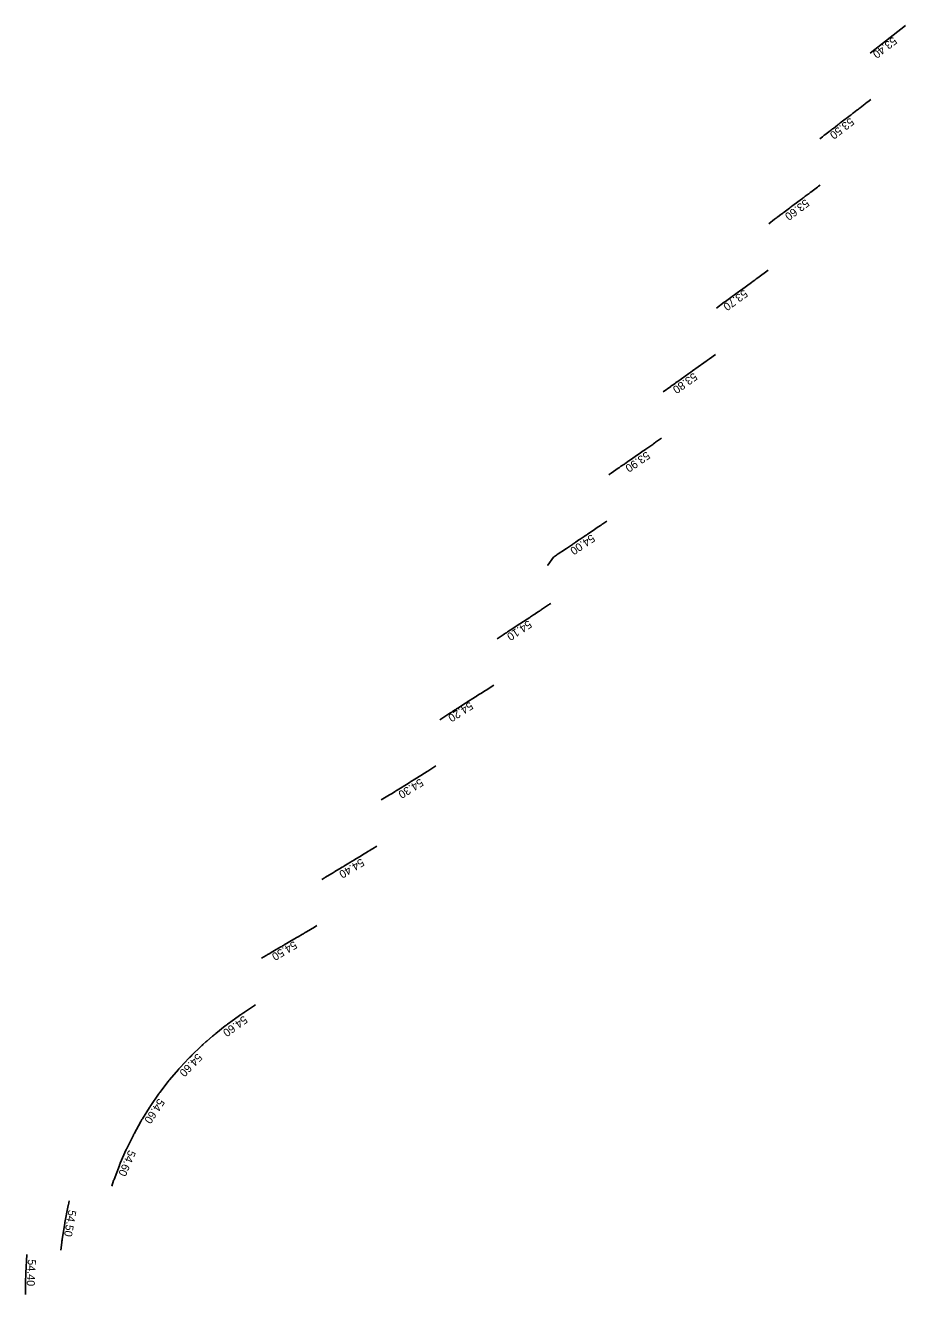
# Model space of a CAD drawing. Extents: x 655100 to 703495, y 6445581 to 6476602.
# Drawn here: x 668502.6 to 668612.5, y 6466301.5 to 6466460 of the extents above; entities that cross this region are included whole.
import ezdxf

# ---------------------------------------------------------------- set-up
doc = ezdxf.new("R2010")
doc.units = 0
for name, color, linetype in [('horis_01', 7, 'Continuous'), ('horis_1', 7, 'Continuous'), ('horis_korgusarv', 7, 'Continuous')]:
    doc.layers.add(name, color=color, linetype=linetype)

msp = doc.modelspace()

# ---------------------------------------------------------------- linework, layer by layer
at = {"layer": 'horis_01'}
for points in [[(668612.52, 6466460), (668608.07, 6466456.54)], [(668601.8, 6466445.85), (668602.13, 6466446.1), (668602.2, 6466446.15), (668602.35, 6466446.27), (668602.43, 6466446.33), (668603.09, 6466446.83), (668603.19, 6466446.91), (668603.29, 6466446.98), (668603.39, 6466447.06), (668603.49, 6466447.14), (668604.01, 6466447.54), (668604.09, 6466447.6), (668604.17, 6466447.66), (668604.36, 6466447.81), (668604.44, 6466447.87), (668604.48, 6466447.9), (668605.6, 6466448.76), (668605.7, 6466448.83), (668605.8, 6466448.91), (668605.9, 6466448.99), (668606, 6466449.07), (668606.42, 6466449.39), (668606.52, 6466449.47), (668606.63, 6466449.55), (668606.73, 6466449.63), (668606.83, 6466449.71), (668607.45, 6466450.19), (668607.51, 6466450.23), (668607.56, 6466450.28), (668607.71, 6466450.39), (668607.79, 6466450.45), (668608.17, 6466450.74)], [(668601.83, 6466440.05), (668601.64, 6466439.9), (668601.6, 6466439.87), (668601.52, 6466439.81), (668601.49, 6466439.79), (668600.68, 6466439.18), (668600.6, 6466439.11), (668600.51, 6466439.05), (668600.42, 6466438.98), (668600.33, 6466438.91), (668599.97, 6466438.65), (668599.89, 6466438.58), (668599.8, 6466438.51), (668599.71, 6466438.45), (668599.62, 6466438.38), (668598.31, 6466437.4), (668598.24, 6466437.34), (668598.1, 6466437.24), (668598.02, 6466437.18), (668597.34, 6466436.67), (668597.24, 6466436.6), (668597.14, 6466436.52), (668597.04, 6466436.45), (668596.94, 6466436.37), (668596.54, 6466436.08), (668596.44, 6466436), (668596.35, 6466435.93), (668596.25, 6466435.86), (668596.15, 6466435.78), (668595.41, 6466435.23)], [(668588.88, 6466424.69), (668589.86, 6466425.41), (668590.02, 6466425.52), (668590.19, 6466425.64), (668590.35, 6466425.76), (668590.51, 6466425.88), (668591.65, 6466426.71), (668591.76, 6466426.79), (668591.92, 6466426.91), (668592.01, 6466426.97), (668593.28, 6466427.9), (668593.48, 6466428.04), (668593.67, 6466428.19), (668593.86, 6466428.33), (668594.06, 6466428.47), (668595.36, 6466429.43)], [(668582.22, 6466414.24), (668583.17, 6466414.91), (668583.24, 6466414.96), (668583.32, 6466415.01), (668583.39, 6466415.06), (668583.46, 6466415.12), (668583.76, 6466415.32), (668583.83, 6466415.38), (668583.91, 6466415.43), (668583.98, 6466415.48), (668584.05, 6466415.53), (668585.45, 6466416.53), (668585.54, 6466416.59), (668585.64, 6466416.66), (668585.68, 6466416.69), (668585.88, 6466416.83), (668585.91, 6466416.85), (668587.3, 6466417.85), (668587.36, 6466417.89), (668587.42, 6466417.93), (668587.48, 6466417.97), (668587.54, 6466418.01), (668587.77, 6466418.18), (668587.83, 6466418.22), (668587.89, 6466418.27), (668587.95, 6466418.31), (668588.01, 6466418.35), (668588.76, 6466418.89)], [(668582.03, 6466408.44), (668581.29, 6466407.92), (668581.17, 6466407.84), (668581.04, 6466407.75), (668580.92, 6466407.66), (668580.8, 6466407.58), (668580.05, 6466407.06), (668579.89, 6466406.95), (668579.74, 6466406.84), (668579.41, 6466406.61), (668579.34, 6466406.56), (668579.27, 6466406.52), (668579.21, 6466406.47), (668579.14, 6466406.42), (668578.04, 6466405.66), (668577.93, 6466405.59), (668577.82, 6466405.51), (668577.61, 6466405.36), (668577.55, 6466405.33), (668577.5, 6466405.29), (668577.45, 6466405.25), (668577.39, 6466405.21), (668576.96, 6466404.92), (668576.87, 6466404.85), (668576.78, 6466404.79), (668576.69, 6466404.73), (668576.6, 6466404.67), (668575.75, 6466404.08), (668575.7, 6466404.05), (668575.6, 6466403.98), (668575.44, 6466403.87)], [(668561.48, 6466383.38), (668562.26, 6466383.89), (668562.39, 6466383.98), (668562.52, 6466384.06), (668562.65, 6466384.14), (668562.78, 6466384.23), (668563.58, 6466384.75), (668563.73, 6466384.85), (668563.88, 6466384.95), (668564.19, 6466385.16), (668564.26, 6466385.2), (668564.32, 6466385.24), (668564.39, 6466385.28), (668564.45, 6466385.32), (668565.56, 6466386.05), (668565.67, 6466386.13), (668565.79, 6466386.2), (668566.01, 6466386.35), (668566.07, 6466386.39), (668566.12, 6466386.42), (668566.18, 6466386.46), (668566.24, 6466386.5), (668566.67, 6466386.78), (668566.76, 6466386.84), (668566.85, 6466386.9), (668566.94, 6466386.96), (668567.03, 6466387.02), (668567.9, 6466387.6), (668567.95, 6466387.63), (668568.04, 6466387.69), (668568.19, 6466387.79)], [(668554.31, 6466373.27), (668555.56, 6466374.07), (668555.65, 6466374.12), (668555.74, 6466374.17), (668555.82, 6466374.23), (668555.91, 6466374.28), (668556.25, 6466374.5), (668556.33, 6466374.56), (668556.42, 6466374.61), (668556.51, 6466374.66), (668556.59, 6466374.72), (668557.54, 6466375.32), (668557.62, 6466375.37), (668557.72, 6466375.44), (668558.64, 6466376.03), (668558.71, 6466376.07), (668558.78, 6466376.12), (668558.86, 6466376.17), (668558.93, 6466376.21), (668559.22, 6466376.4), (668559.3, 6466376.45), (668559.37, 6466376.5), (668559.44, 6466376.54), (668559.52, 6466376.59), (668559.82, 6466376.78), (668559.89, 6466376.83), (668559.97, 6466376.88), (668560.04, 6466376.93), (668560.11, 6466376.97), (668561.08, 6466377.59)], [(668553.84, 6466367.49), (668552.83, 6466366.86), (668552.66, 6466366.75), (668552.49, 6466366.65), (668552.33, 6466366.54), (668552.16, 6466366.44), (668551, 6466365.72), (668550.87, 6466365.63), (668550.72, 6466365.54), (668550.66, 6466365.51), (668550.61, 6466365.47), (668550.43, 6466365.36), (668550.37, 6466365.32), (668548.99, 6466364.47), (668548.91, 6466364.42), (668548.83, 6466364.37), (668548.75, 6466364.32), (668548.67, 6466364.27), (668548.36, 6466364.07), (668548.28, 6466364.03), (668548.2, 6466363.98), (668548.12, 6466363.93), (668548.04, 6466363.88), (668547.02, 6466363.25)], [(668546.47, 6466357.47), (668545.92, 6466357.14), (668545.84, 6466357.09), (668545.75, 6466357.04), (668545.58, 6466356.93), (668545.54, 6466356.91), (668545.5, 6466356.88), (668545.46, 6466356.85), (668545.42, 6466356.83), (668544.55, 6466356.3), (668544.37, 6466356.2), (668544.19, 6466356.09), (668543.71, 6466355.79), (668543.66, 6466355.76), (668543.6, 6466355.73), (668543.47, 6466355.65), (668543.39, 6466355.6), (668543.09, 6466355.42), (668542.94, 6466355.33), (668542.35, 6466354.97), (668542.24, 6466354.9), (668542.13, 6466354.84), (668541.92, 6466354.71), (668541.86, 6466354.68), (668541.81, 6466354.65), (668541.76, 6466354.61), (668541.7, 6466354.58), (668541.23, 6466354.3), (668541.13, 6466354.24), (668541.04, 6466354.18), (668540.94, 6466354.12), (668540.85, 6466354.06), (668540.06, 6466353.59), (668540.01, 6466353.56), (668539.96, 6466353.54), (668539.92, 6466353.51), (668539.87, 6466353.48), (668539.6, 6466353.32)], [(668532.06, 6466343.48), (668532.62, 6466343.81), (668532.72, 6466343.86), (668532.81, 6466343.92), (668532.91, 6466343.97), (668533, 6466344.03), (668533.46, 6466344.3), (668533.68, 6466344.43), (668533.9, 6466344.55), (668534.46, 6466344.88), (668534.57, 6466344.94), (668534.67, 6466345.01), (668534.78, 6466345.07), (668534.89, 6466345.13), (668536.09, 6466345.84), (668536.18, 6466345.89), (668536.27, 6466345.94), (668536.44, 6466346.05), (668536.53, 6466346.1), (668536.62, 6466346.15), (668537.17, 6466346.48), (668537.28, 6466346.54), (668537.39, 6466346.6), (668537.49, 6466346.67), (668537.6, 6466346.73), (668538.24, 6466347.11), (668538.31, 6466347.15), (668538.39, 6466347.2), (668538.46, 6466347.24), (668538.54, 6466347.28), (668538.98, 6466347.55)], [(668513.35, 6466315.02), (668513.58, 6466315.71), (668513.59, 6466315.74), (668513.6, 6466315.77), (668513.61, 6466315.8), (668513.63, 6466315.83), (668514.3, 6466317.59), (668514.32, 6466317.66), (668514.35, 6466317.73), (668514.38, 6466317.8), (668514.41, 6466317.87), (668515.15, 6466319.57), (668515.16, 6466319.6), (668515.18, 6466319.63), (668515.19, 6466319.66), (668515.21, 6466319.69), (668516.04, 6466321.38), (668516.06, 6466321.42), (668516.08, 6466321.47), (668516.11, 6466321.51), (668516.13, 6466321.55), (668516.97, 6466323.07), (668517.02, 6466323.15), (668517.07, 6466323.24), (668517.12, 6466323.32), (668517.17, 6466323.41), (668518.04, 6466324.81), (668518.08, 6466324.88), (668518.13, 6466324.95), (668518.18, 6466325.02), (668518.22, 6466325.09), (668519.19, 6466326.49), (668519.23, 6466326.54), (668519.27, 6466326.6), (668519.31, 6466326.65), (668519.35, 6466326.71), (668520.4, 6466328.08), (668520.44, 6466328.13), (668520.49, 6466328.19), (668520.53, 6466328.24), (668520.57, 6466328.29), (668521.67, 6466329.58), (668521.73, 6466329.65), (668521.78, 6466329.71), (668521.84, 6466329.77), (668521.9, 6466329.84), (668522.98, 6466330.99), (668523.07, 6466331.08), (668523.16, 6466331.17), (668523.25, 6466331.26), (668523.34, 6466331.35), (668524.49, 6466332.46), (668524.55, 6466332.52), (668524.61, 6466332.57), (668524.67, 6466332.63), (668524.73, 6466332.68), (668525.11, 6466333.01), (668525.24, 6466333.12), (668525.93, 6466333.73), (668526.04, 6466333.82), (668526.14, 6466333.91), (668526.25, 6466334), (668526.35, 6466334.08), (668527.52, 6466335.01), (668527.61, 6466335.08), (668527.7, 6466335.15), (668527.72, 6466335.17), (668527.75, 6466335.19), (668527.77, 6466335.21), (668527.79, 6466335.22), (668528.09, 6466335.44), (668528.23, 6466335.54), (668529.29, 6466336.31), (668529.36, 6466336.36), (668529.43, 6466336.41), (668529.5, 6466336.46), (668529.58, 6466336.51), (668529.87, 6466336.7), (668529.94, 6466336.75), (668530.01, 6466336.79), (668530.09, 6466336.84), (668530.16, 6466336.89), (668531.16, 6466337.55), (668531.18, 6466337.56), (668531.19, 6466337.57), (668531.21, 6466337.58), (668531.22, 6466337.59), (668531.31, 6466337.65)], [(668508.04, 6466313.16), (668507.93, 6466312.68), (668507.92, 6466312.66), (668507.91, 6466312.63), (668507.91, 6466312.6), (668507.9, 6466312.58), (668507.49, 6466310.47), (668507.48, 6466310.45), (668507.48, 6466310.42), (668507.47, 6466310.4), (668507.47, 6466310.37), (668507.15, 6466308.34), (668507.14, 6466308.25), (668507.12, 6466308.15), (668507.11, 6466308.05), (668507.1, 6466307.95), (668506.99, 6466307.01)], [(668502.73, 6466306.48), (668502.61, 6466304.12), (668502.61, 6466304.1), (668502.61, 6466304.08), (668502.61, 6466304.06), (668502.6, 6466304.04), (668502.58, 6466303.04), (668502.58, 6466302.89), (668502.58, 6466302.75), (668502.58, 6466302.6), (668502.57, 6466302.46), (668502.55, 6466301.57), (668502.55, 6466301.55), (668502.55, 6466301.49), (668502.55, 6466301.45)]]:
    msp.add_lwpolyline(points, dxfattribs=at)
at = {"layer": 'horis_1'}
for points in [[(668575.18, 6466398.07), (668574.7, 6466397.75), (668574.62, 6466397.7), (668574.55, 6466397.64), (668574.47, 6466397.59), (668574.39, 6466397.54), (668574, 6466397.27), (668573.81, 6466397.15), (668573.63, 6466397.02), (668572.84, 6466396.49), (668572.76, 6466396.43), (668572.68, 6466396.38), (668572.48, 6466396.24), (668572.4, 6466396.19), (668572.36, 6466396.16), (668571.99, 6466395.91), (668571.85, 6466395.82), (668571.71, 6466395.72), (668571.36, 6466395.48), (668571.28, 6466395.43), (668571.2, 6466395.38), (668571.05, 6466395.28), (668570.97, 6466395.23), (668570.9, 6466395.17), (668570.14, 6466394.67), (668569.95, 6466394.54), (668569.76, 6466394.41), (668569.24, 6466394.06), (668569.18, 6466394.02), (668569.13, 6466393.99), (668568.98, 6466393.89), (668568.89, 6466393.83), (668568.52, 6466393.58)], [(668567.78, 6466392.53), (668567.8, 6466392.56), (668568.52, 6466393.58)]]:
    msp.add_lwpolyline(points, dxfattribs=at)

# ---------------------------------------------------------------- texts
at = {"layer": 'horis_korgusarv'}
for s, rotation, p in [('53.40', 217.8721, (668610.95, 6466458.64)), ('53.50', 217.5491, (668605.6, 6466448.53)), ('53.60', 216.869, (668600.01, 6466438.36)), ('53.70', 216.1269, (668592.33, 6466427.05)), ('53.80', 215.4226, (668586.05, 6466416.67)), ('53.90', 214.7439, (668580.15, 6466406.83)), ('54.00', 214.0279, (668573.28, 6466396.48)), ('54.10', 213.2739, (668565.4, 6466385.74)), ('54.20', 212.5711, (668558.08, 6466375.56)), ('54.30', 211.8922, (668551.88, 6466365.97)), ('54.40', 211.1879, (668544.5, 6466355.98)), ('54.50', 210.4288, (668536.12, 6466345.67)), ('54.60', 215.8703, (668529.84, 6466336.35)), ('54.60', 225.7262, (668524.05, 6466331.66)), ('54.60', 236.5548, (668519.2, 6466326.03)), ('54.60', 246.7, (668515.47, 6466319.59)), ('54.50', 260.241, (668507.94, 6466312.08)), ('54.40', 267.1108, (668502.88, 6466305.88))]:
    msp.add_text(s, height=1, rotation=rotation, dxfattribs=at).set_placement(p)

doc.saveas('drawing.dxf')
